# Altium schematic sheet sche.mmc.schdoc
size 297 x 209 mm; Width: 1170; Height: 825; Symbol: Sheet-Symbol_A4; Company: 嘉立创EDA; Version: V1.0; Page Size: A4; @Project Name: 木马派(Mumap) Linux卡片电脑-RV1106G; @Page Count: 10; @Update Date: 2024-12-29; @Create Date: 2024-11-26; @Schematic Name: Schematic1; @Page No: 6; @Page Name: SPI Flash; Border: 1; Title Block Position: 3; Region Start: 1; X Region Count: 6; Y Region Count: 4; Blade Width: 10; Title Block: 1; @Board Name: NandFlash; @Create Time: 22:37:04; @Update Time: 16:11:56; Device: Sheet-Symbol_A4
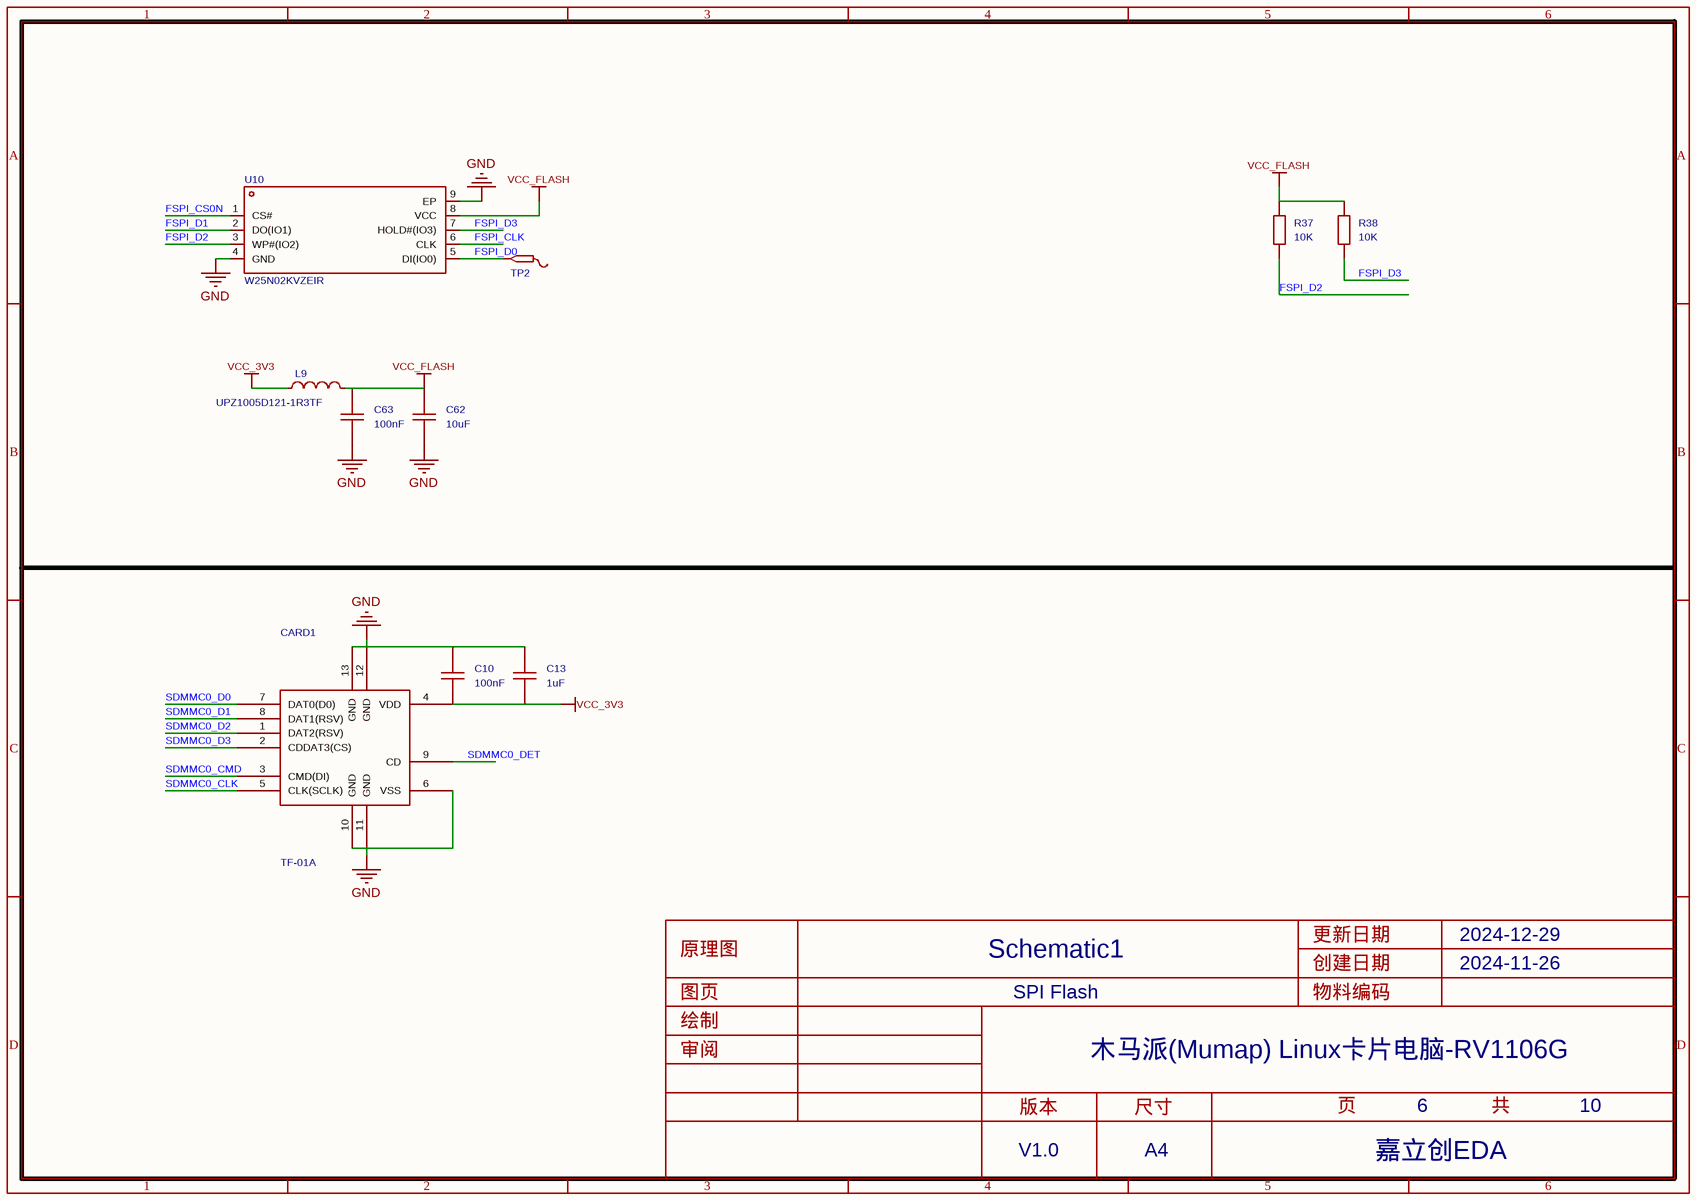
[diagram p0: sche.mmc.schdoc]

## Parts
C10  100nF  [C0402]
C13  1uF  [C0402]
C62  10uF  [C0603]
C63  100nF  [C0402]
CARD1  TF-01A  [TF-SMD_TF-01A]
L9  UPZ1005D121-1R3TF  [L0402]
R37  10K  [R0402]
R38  10K  [R0402]
TP2  (no value)  [Test-Point-0.5mm]
U10  W25N02KVZEIR  [WSON-8_L8.0-W6.0-P1.27-TL-EP-1]

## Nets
GND: C10.2 C13.2 C62.1 C63.1 CARD1.6(VSS) CARD1.10(GND) CARD1.11(GND) CARD1.12(GND) CARD1.13(GND) U10.4(GND) U10.9(EP)
VCC_3V3: C10.1 C13.1 CARD1.4(VDD) L9.1
VCC_FLASH: C62.2 C63.2 L9.2 R37.2 R38.2 U10.8(VCC)
FSPI_CLK: U10.6(CLK)
FSPI_CS0N: U10.1(CS#)
FSPI_D0: TP2.1 U10.5(DI(IO0))
FSPI_D1: U10.2(DO(IO1))
FSPI_D2: R37.1 U10.3(WP#(IO2))
FSPI_D3: R38.1 U10.7(HOLD#(IO3))
SDMMC0_CLK: CARD1.5(CLK(SCLK))
SDMMC0_CMD: CARD1.3(CMD(DI))
SDMMC0_D0: CARD1.7(DAT0(D0))
SDMMC0_D1: CARD1.8(DAT1(RSV))
SDMMC0_D2: CARD1.1(DAT2(RSV))
SDMMC0_D3: CARD1.2(CDDAT3(CS))
SDMMC0_DET: CARD1.9(CD)

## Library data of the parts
C10 C13 = CAP_0402: Symbol: CapAcitance; 3D Model: 36a51122f27c49738f86b3bfa98863e0; 3D Model Transform: 39.37,19.685,0,0,0,0,0,0,0; ConvertToPcb: yes; ModelName: C0402_L1.0-W0.5-H0.5
C62 = CAP_0603: Symbol: CapAcitance; ConvertToPcb: yes; ModelId: ac125912035d415993ca9572d50418b1; ModelName: C0603_L1.6-W0.8-H0.8; ModelTransform: 62.992,31.496,0,0,0,0,0,0,0
C63 = CAP_0402: Symbol: CapAcitance; ConvertToPcb: yes; ModelId: 36a51122f27c49738f86b3bfa98863e0; ModelName: C0402_L1.0-W0.5-H0.5; ModelTransform: 39.37,19.685,0,0,0,0,0,0,0
CARD1 = TF-01A_C91145: 卡连接方式:自弹式;卡类型:MicroSD卡(TF卡);连接器类型:卡座;本体最大高度:1.85mm;工作温度范围:-;; Manufacturer: 韩国韩荣; 3D Model: 5b4be50223494db9bf5c92b2cb3c1375; 3D Model Transform: 629.92,600.393,0,0,0,0,0,-85.473,-23.622; Card Connection Mode: 自弹式; Connector Type: 卡座; Supplementary Features: 带定位柱; Maximum Body Height: 1.85mm; AddInBom: yes; ModelName: TF-SMD_L14.8-W14.5-H1.9-P1.1
L9 = UPZ1005D121-1R3TF: 标称阻抗@测试频率:120Ω@100MHz;误差:±25%;直流电阻(RDC):90mΩ;; Manufacturer: Sunlord(顺络); AddInBom: yes; ModelId: d8d36575a3234d4790bfa765c88664a7; ModelName: L0402_L1.0-W0.5-H0.5_BEAD; ModelTransform: 39.37,19.685,0,0,0,0,0,0.0005,0; Tolerance: ±25%; DC Resistance: 90mΩ; Current Rating: 1.3A; Circuits: 1
R37 R38 = Res_0402: Symbol: 电阻; ConvertToPcb: yes; ModelId: 671aefced39d4c318694bba8bd8efd39; ModelName: R0402_L1.0-W0.5-H0.5; ModelTransform: 39.37,19.685,0,0,0,0,0,0.0005,0
TP2 = Test-Point: Test Point 测试点; AddInBom: yes
U10 = W25N02KVZEIR: 3v 2位SLC qspin和闪存 2/4SPI 逻辑读取和顺序读取; Manufacturer: WINBOND(华邦); AddInBom: yes; ModelId: 9b0b95cb42c44ddaa75bcc393c15d437; ModelTransform: 314.96,236.22,0,0,0,0,0,0,0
